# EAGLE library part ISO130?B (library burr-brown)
Isolation Amplifier Precision, Lowest Cost
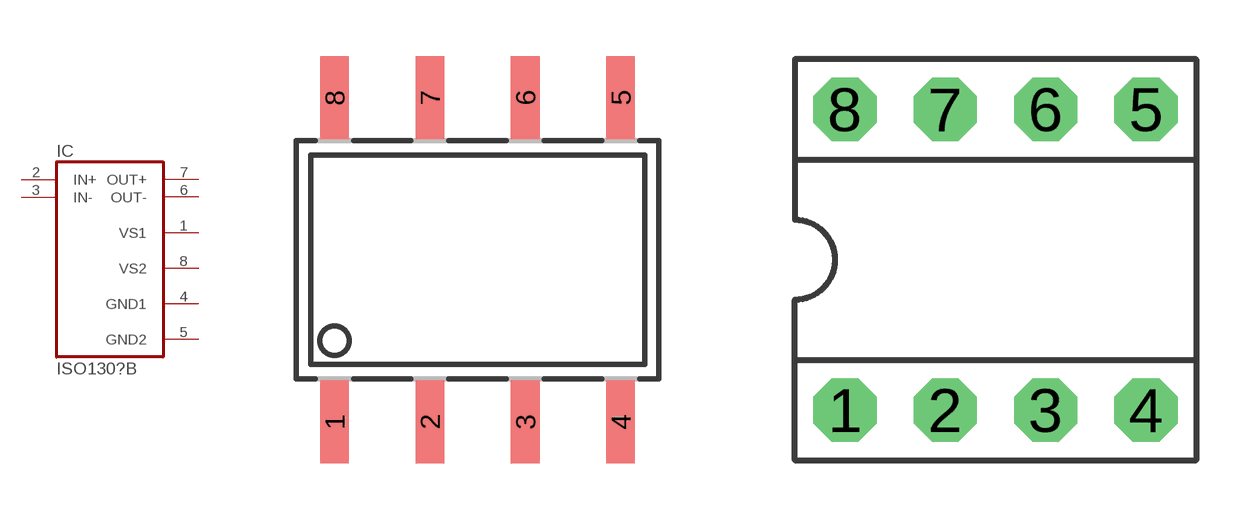
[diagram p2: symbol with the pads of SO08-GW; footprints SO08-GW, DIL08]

Designator prefix IC

## ISO130UB (OC_FARNELL: unknown; OC_NEWARK: unknown)  [SO08-GW]
1  VS1  pwr
2  IN+  in
3  IN-  in
4  GND1  pwr
5  GND2  pwr
6  OUT-  out
7  OUT+  out
8  VS2  pwr

## ISO130PB (OC_FARNELL: unknown; OC_NEWARK: unknown)  [DIL08]
Pads as for SO08-GW

## Footprint SO08-GW (pad centres in mm)
Small Outline Package, gull wing
smd 0.762 x 2.21: 1 -3.81,-4.318; 2 -1.27,-4.318; 3 1.27,-4.318; 4 3.81,-4.318; 5 3.81,4.318; 6 1.27,4.318; 7 -1.27,4.318; 8 -3.81,4.318

## Footprint DIL08 (pad centres in mm)
Dual In Line
drill 0.813 pad 1.6 octagon: 1 -3.81,-3.81; 2 -1.27,-3.81; 3 1.27,-3.81; 4 3.81,-3.81; 5 3.81,3.81; 6 1.27,3.81; 7 -1.27,3.81; 8 -3.81,3.81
